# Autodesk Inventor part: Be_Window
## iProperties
Shininess: 64.0
Length Units: 11269
Angle Units: 11279
Time Units: 11290
Mass Units: 11283
Length Display Precision: 3
Angle Display Precision: 2
Compacted: True
Part Number: Be_Window
Document SubType Name: Modeling
Created: 2004-07
Project: Mucap
Material: Aluminum-6061
Description: Mucap, Beryllium Window
Designer: John Blackburn
Manufacturer: Standard
Standards Organization: Custom
Density: 0.0
Volumn: 0.0
Area: 0.0
PropertySet Name: Model Information
Control State: 0
Master: False
Checked Out: False
Title: Mucap, Be Window
Subject: Mucap
Author: John Blackburn
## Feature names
1. Revolution2
